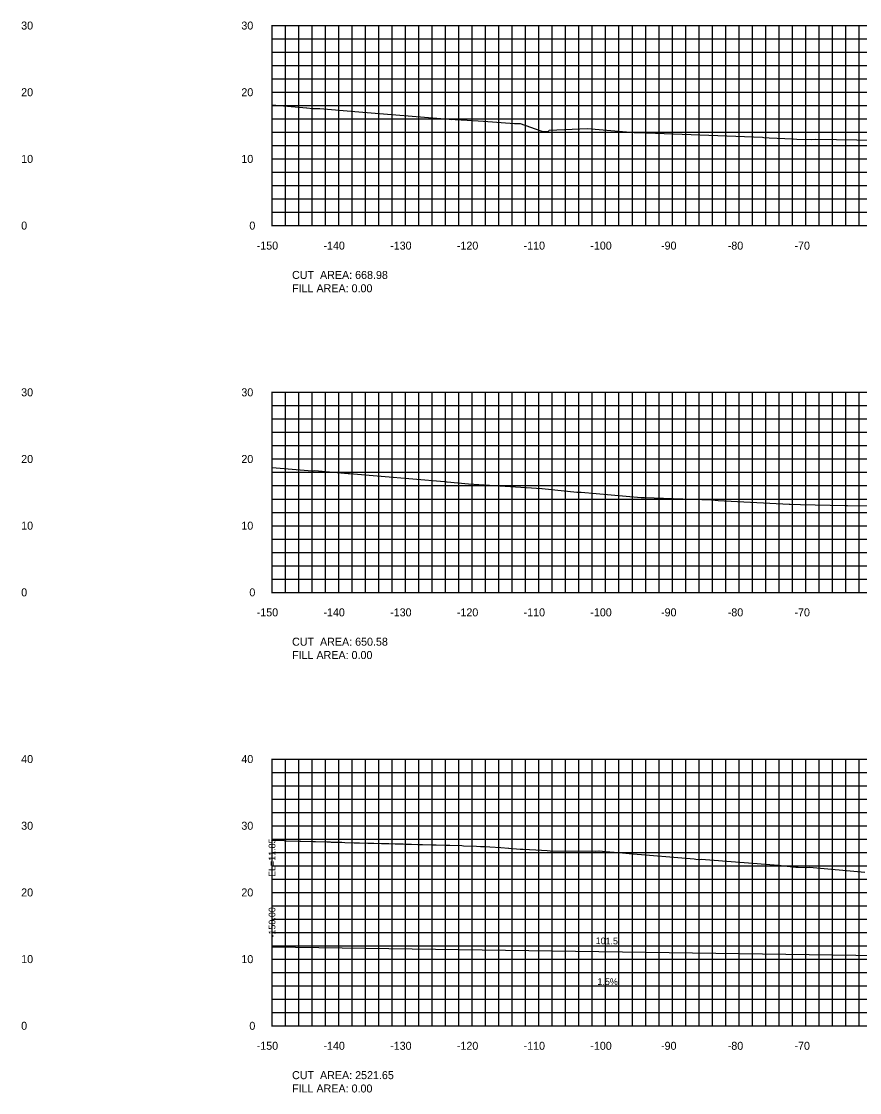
# Model space of a CAD drawing. Extents: x 1797789 to 1803805, y 249066 to 250293.
# Drawn here: x 1803123.4 to 1803249.1, y 250089.4 to 250250 of the extents above; entities that cross this region are included whole.
import ezdxf

# ---------------------------------------------------------------- set-up
doc = ezdxf.new("R2010")
doc.units = 0
for name, color, linetype in [('10', 7, 'Continuous'), ('3', 7, 'Continuous'), ('31', 7, 'Continuous'), ('4', 7, 'Continuous'), ('60', 7, 'Continuous'), ('ANNO-TXT', 7, 'Continuous'), ('CL-CNST', 7, 'Continuous'), ('Level 62', 7, 'Continuous'), ('M-ROADS', 7, 'Continuous')]:
    doc.layers.add(name, color=color, linetype=linetype)

msp = doc.modelspace()

# ---------------------------------------------------------------- linework, layer by layer
msp.add_line((1803161, 250111.29), (1803161, 250113.29))
at = {"layer": '60'}
for p, q in [((1803160.94, 250249.43), (1803161, 250249.43)), ((1803161, 250219.43), (1803161, 250249.43)), ((1803160.94, 250239.43), (1803161, 250239.43)), ((1803160.94, 250229.43), (1803161, 250229.43)), ((1803160.94, 250219.43), (1803161, 250219.43)), ((1803161, 250219.43), (1803461, 250219.43)), ((1803161, 250219.37), (1803161, 250219.43)), ((1803171, 250219.37), (1803171, 250219.43)), ((1803181, 250219.37), (1803181, 250219.43)), ((1803191, 250219.37), (1803191, 250219.43)), ((1803201, 250219.37), (1803201, 250219.43)), ((1803211, 250219.37), (1803211, 250219.43)), ((1803221, 250219.37), (1803221, 250219.43)), ((1803231, 250219.37), (1803231, 250219.43)), ((1803241, 250219.37), (1803241, 250219.43)), ((1803160.94, 250194.43), (1803161, 250194.43)), ((1803161, 250164.43), (1803161, 250194.43)), ((1803160.94, 250184.43), (1803161, 250184.43)), ((1803160.94, 250174.43), (1803161, 250174.43)), ((1803160.94, 250164.43), (1803161, 250164.43)), ((1803161, 250164.43), (1803461, 250164.43)), ((1803161, 250164.37), (1803161, 250164.43)), ((1803171, 250164.37), (1803171, 250164.43)), ((1803181, 250164.37), (1803181, 250164.43)), ((1803191, 250164.37), (1803191, 250164.43)), ((1803201, 250164.37), (1803201, 250164.43)), ((1803211, 250164.37), (1803211, 250164.43)), ((1803221, 250164.37), (1803221, 250164.43)), ((1803231, 250164.37), (1803231, 250164.43)), ((1803241, 250164.37), (1803241, 250164.43)), ((1803160.94, 250139.43), (1803161, 250139.43)), ((1803161, 250099.43), (1803161, 250139.43)), ((1803160.94, 250129.43), (1803161, 250129.43)), ((1803160.94, 250119.43), (1803161, 250119.43)), ((1803160.94, 250109.43), (1803161, 250109.43)), ((1803160.94, 250099.43), (1803161, 250099.43)), ((1803161, 250099.43), (1803461, 250099.43)), ((1803161, 250099.37), (1803161, 250099.43)), ((1803171, 250099.37), (1803171, 250099.43)), ((1803181, 250099.37), (1803181, 250099.43)), ((1803191, 250099.37), (1803191, 250099.43)), ((1803201, 250099.37), (1803201, 250099.43)), ((1803211, 250099.37), (1803211, 250099.43)), ((1803221, 250099.37), (1803221, 250099.43)), ((1803231, 250099.37), (1803231, 250099.43)), ((1803241, 250099.37), (1803241, 250099.43))]:
    msp.add_line(p, q, dxfattribs=at)
at = {"layer": 'CL-CNST'}
msp.add_lwpolyline([(1803161, 250111.29), (1803262.5, 250109.8), (1803263.5, 250109.76), (1803270.5, 250109.65), (1803270.5, 250109.65), (1803270.83, 250109.65), (1803271, 250109.15), (1803273, 250109.31), (1803277, 250109.4), (1803311, 250110.15), (1803345, 250109.4), (1803349, 250109.31), (1803351, 250109.15), (1803351.17, 250109.65), (1803351.5, 250109.65), (1803351.5, 250109.65), (1803358.5, 250109.76), (1803359.5, 250109.8), (1803461, 250109.89)], dxfattribs=at)
at = {"layer": 'Level 62'}
for p, q in [((1803161, 250249.43), (1803461, 250249.43)), ((1803161, 250219.43), (1803161, 250249.43)), ((1803163, 250219.43), (1803163, 250249.43)), ((1803165, 250219.43), (1803165, 250249.43)), ((1803167, 250219.43), (1803167, 250249.43)), ((1803169, 250219.43), (1803169, 250249.43)), ((1803171, 250219.43), (1803171, 250249.43)), ((1803173, 250219.43), (1803173, 250249.43)), ((1803175, 250219.43), (1803175, 250249.43)), ((1803177, 250219.43), (1803177, 250249.43)), ((1803179, 250219.43), (1803179, 250249.43)), ((1803181, 250219.43), (1803181, 250249.43)), ((1803183, 250219.43), (1803183, 250249.43)), ((1803185, 250219.43), (1803185, 250249.43)), ((1803187, 250219.43), (1803187, 250249.43)), ((1803189, 250219.43), (1803189, 250249.43)), ((1803191, 250219.43), (1803191, 250249.43)), ((1803193, 250219.43), (1803193, 250249.43)), ((1803195, 250219.43), (1803195, 250249.43)), ((1803197, 250219.43), (1803197, 250249.43)), ((1803199, 250219.43), (1803199, 250249.43)), ((1803201, 250219.43), (1803201, 250249.43)), ((1803203, 250219.43), (1803203, 250249.43)), ((1803205, 250219.43), (1803205, 250249.43)), ((1803207, 250219.43), (1803207, 250249.43)), ((1803209, 250219.43), (1803209, 250249.43)), ((1803211, 250219.43), (1803211, 250249.43)), ((1803213, 250219.43), (1803213, 250249.43)), ((1803215, 250219.43), (1803215, 250249.43)), ((1803217, 250219.43), (1803217, 250249.43)), ((1803219, 250219.43), (1803219, 250249.43)), ((1803221, 250219.43), (1803221, 250249.43)), ((1803223, 250219.43), (1803223, 250249.43)), ((1803225, 250219.43), (1803225, 250249.43)), ((1803227, 250219.43), (1803227, 250249.43)), ((1803229, 250219.43), (1803229, 250249.43)), ((1803231, 250219.43), (1803231, 250249.43)), ((1803233, 250219.43), (1803233, 250249.43)), ((1803235, 250219.43), (1803235, 250249.43)), ((1803237, 250219.43), (1803237, 250249.43)), ((1803239, 250219.43), (1803239, 250249.43)), ((1803241, 250219.43), (1803241, 250249.43)), ((1803243, 250219.43), (1803243, 250249.43)), ((1803245, 250219.43), (1803245, 250249.43)), ((1803247, 250219.43), (1803247, 250249.43)), ((1803249, 250219.43), (1803249, 250249.43)), ((1803161, 250247.43), (1803461, 250247.43)), ((1803161, 250245.43), (1803461, 250245.43)), ((1803161, 250243.43), (1803461, 250243.43)), ((1803161, 250241.43), (1803461, 250241.43)), ((1803161, 250239.43), (1803461, 250239.43)), ((1803161, 250237.43), (1803461, 250237.43)), ((1803161, 250235.43), (1803461, 250235.43)), ((1803161, 250233.43), (1803461, 250233.43)), ((1803161, 250231.43), (1803461, 250231.43)), ((1803161, 250229.43), (1803461, 250229.43)), ((1803161, 250227.43), (1803461, 250227.43)), ((1803161, 250225.43), (1803461, 250225.43)), ((1803161, 250223.43), (1803461, 250223.43)), ((1803161, 250221.43), (1803461, 250221.43)), ((1803161, 250219.43), (1803461, 250219.43)), ((1803161, 250194.43), (1803461, 250194.43)), ((1803161, 250164.43), (1803161, 250194.43)), ((1803163, 250164.43), (1803163, 250194.43)), ((1803165, 250164.43), (1803165, 250194.43)), ((1803167, 250164.43), (1803167, 250194.43)), ((1803169, 250164.43), (1803169, 250194.43)), ((1803171, 250164.43), (1803171, 250194.43)), ((1803173, 250164.43), (1803173, 250194.43)), ((1803175, 250164.43), (1803175, 250194.43)), ((1803177, 250164.43), (1803177, 250194.43)), ((1803179, 250164.43), (1803179, 250194.43)), ((1803181, 250164.43), (1803181, 250194.43)), ((1803183, 250164.43), (1803183, 250194.43)), ((1803185, 250164.43), (1803185, 250194.43)), ((1803187, 250164.43), (1803187, 250194.43)), ((1803189, 250164.43), (1803189, 250194.43)), ((1803191, 250164.43), (1803191, 250194.43)), ((1803193, 250164.43), (1803193, 250194.43)), ((1803195, 250164.43), (1803195, 250194.43)), ((1803197, 250164.43), (1803197, 250194.43)), ((1803199, 250164.43), (1803199, 250194.43)), ((1803201, 250164.43), (1803201, 250194.43)), ((1803203, 250164.43), (1803203, 250194.43)), ((1803205, 250164.43), (1803205, 250194.43)), ((1803207, 250164.43), (1803207, 250194.43)), ((1803209, 250164.43), (1803209, 250194.43)), ((1803211, 250164.43), (1803211, 250194.43)), ((1803213, 250164.43), (1803213, 250194.43)), ((1803215, 250164.43), (1803215, 250194.43)), ((1803217, 250164.43), (1803217, 250194.43)), ((1803219, 250164.43), (1803219, 250194.43)), ((1803221, 250164.43), (1803221, 250194.43)), ((1803223, 250164.43), (1803223, 250194.43)), ((1803225, 250164.43), (1803225, 250194.43)), ((1803227, 250164.43), (1803227, 250194.43)), ((1803229, 250164.43), (1803229, 250194.43)), ((1803231, 250164.43), (1803231, 250194.43)), ((1803233, 250164.43), (1803233, 250194.43)), ((1803235, 250164.43), (1803235, 250194.43)), ((1803237, 250164.43), (1803237, 250194.43)), ((1803239, 250164.43), (1803239, 250194.43)), ((1803241, 250164.43), (1803241, 250194.43)), ((1803243, 250164.43), (1803243, 250194.43)), ((1803245, 250164.43), (1803245, 250194.43)), ((1803247, 250164.43), (1803247, 250194.43)), ((1803249, 250164.43), (1803249, 250194.43)), ((1803161, 250192.43), (1803461, 250192.43)), ((1803161, 250190.43), (1803461, 250190.43)), ((1803161, 250188.43), (1803461, 250188.43)), ((1803161, 250186.43), (1803461, 250186.43)), ((1803161, 250184.43), (1803461, 250184.43)), ((1803161, 250182.43), (1803461, 250182.43)), ((1803161, 250180.43), (1803461, 250180.43)), ((1803161, 250178.43), (1803461, 250178.43)), ((1803161, 250176.43), (1803461, 250176.43)), ((1803161, 250174.43), (1803461, 250174.43)), ((1803161, 250172.43), (1803461, 250172.43)), ((1803161, 250170.43), (1803461, 250170.43)), ((1803161, 250168.43), (1803461, 250168.43)), ((1803161, 250166.43), (1803461, 250166.43)), ((1803161, 250164.43), (1803461, 250164.43)), ((1803161, 250139.43), (1803461, 250139.43)), ((1803161, 250099.43), (1803161, 250139.43)), ((1803163, 250099.43), (1803163, 250139.43)), ((1803165, 250099.43), (1803165, 250139.43)), ((1803167, 250099.43), (1803167, 250139.43)), ((1803169, 250099.43), (1803169, 250139.43)), ((1803171, 250099.43), (1803171, 250139.43)), ((1803173, 250099.43), (1803173, 250139.43)), ((1803175, 250099.43), (1803175, 250139.43)), ((1803177, 250099.43), (1803177, 250139.43)), ((1803179, 250099.43), (1803179, 250139.43)), ((1803181, 250099.43), (1803181, 250139.43)), ((1803183, 250099.43), (1803183, 250139.43)), ((1803185, 250099.43), (1803185, 250139.43)), ((1803187, 250099.43), (1803187, 250139.43)), ((1803189, 250099.43), (1803189, 250139.43)), ((1803191, 250099.43), (1803191, 250139.43)), ((1803193, 250099.43), (1803193, 250139.43)), ((1803195, 250099.43), (1803195, 250139.43)), ((1803197, 250099.43), (1803197, 250139.43)), ((1803199, 250099.43), (1803199, 250139.43)), ((1803201, 250099.43), (1803201, 250139.43)), ((1803203, 250099.43), (1803203, 250139.43)), ((1803205, 250099.43), (1803205, 250139.43)), ((1803207, 250099.43), (1803207, 250139.43)), ((1803209, 250099.43), (1803209, 250139.43)), ((1803211, 250099.43), (1803211, 250139.43)), ((1803213, 250099.43), (1803213, 250139.43)), ((1803215, 250099.43), (1803215, 250139.43)), ((1803217, 250099.43), (1803217, 250139.43)), ((1803219, 250099.43), (1803219, 250139.43)), ((1803221, 250099.43), (1803221, 250139.43)), ((1803223, 250099.43), (1803223, 250139.43)), ((1803225, 250099.43), (1803225, 250139.43)), ((1803227, 250099.43), (1803227, 250139.43)), ((1803229, 250099.43), (1803229, 250139.43)), ((1803231, 250099.43), (1803231, 250139.43)), ((1803233, 250099.43), (1803233, 250139.43)), ((1803235, 250099.43), (1803235, 250139.43)), ((1803237, 250099.43), (1803237, 250139.43)), ((1803239, 250099.43), (1803239, 250139.43)), ((1803241, 250099.43), (1803241, 250139.43)), ((1803243, 250099.43), (1803243, 250139.43)), ((1803245, 250099.43), (1803245, 250139.43)), ((1803247, 250099.43), (1803247, 250139.43)), ((1803249, 250099.43), (1803249, 250139.43)), ((1803161, 250137.43), (1803461, 250137.43)), ((1803161, 250135.43), (1803461, 250135.43)), ((1803161, 250133.43), (1803461, 250133.43)), ((1803161, 250131.43), (1803461, 250131.43)), ((1803161, 250129.43), (1803461, 250129.43)), ((1803161, 250127.43), (1803461, 250127.43)), ((1803161, 250125.43), (1803461, 250125.43)), ((1803161, 250123.43), (1803461, 250123.43)), ((1803161, 250121.43), (1803461, 250121.43)), ((1803161, 250119.43), (1803461, 250119.43)), ((1803161, 250117.43), (1803461, 250117.43)), ((1803161, 250115.43), (1803461, 250115.43)), ((1803161, 250113.43), (1803461, 250113.43)), ((1803161, 250111.43), (1803461, 250111.43)), ((1803161, 250109.43), (1803461, 250109.43)), ((1803161, 250107.43), (1803461, 250107.43)), ((1803161, 250105.43), (1803461, 250105.43)), ((1803161, 250103.43), (1803461, 250103.43)), ((1803161, 250101.43), (1803461, 250101.43)), ((1803161, 250099.43), (1803461, 250099.43))]:
    msp.add_line(p, q, dxfattribs=at)
at = {"layer": 'M-ROADS'}
for points in [[(1803161, 250237.55), (1803166.15, 250237.11), (1803166.19, 250237.1), (1803167.08, 250236.99), (1803167.31, 250236.97), (1803167.32, 250236.97), (1803167.71, 250237.01), (1803168.12, 250236.98), (1803168.14, 250236.98), (1803173.99, 250236.49), (1803187.56, 250235.38), (1803187.92, 250235.34), (1803188.29, 250235.37), (1803188.45, 250235.36), (1803189.36, 250235.31), (1803189.59, 250235.28), (1803190.26, 250235.22), (1803192.7, 250235.07), (1803197.36, 250234.76), (1803197.54, 250234.75), (1803198.17, 250234.74), (1803201.27, 250233.62), (1803201.68, 250233.54), (1803201.75, 250233.54), (1803202.01, 250233.54), (1803202.13, 250233.53), (1803202.28, 250233.52), (1803202.45, 250233.53), (1803202.53, 250233.72), (1803208.29, 250233.97), (1803215.29, 250233.37), (1803215.37, 250233.37), (1803215.77, 250233.39), (1803234.52, 250232.67), (1803234.72, 250232.66), (1803235.49, 250232.61), (1803239.06, 250232.42), (1803239.11, 250232.42), (1803239.64, 250232.4), (1803241.88, 250232.36), (1803242.49, 250232.37), (1803257.91, 250232.13)], [(1803161, 250183.17), (1803167.02, 250182.64), (1803167.16, 250182.66), (1803167.42, 250182.68), (1803172.41, 250182.23), (1803172.62, 250182.24), (1803186.85, 250181.04), (1803187.16, 250180.99), (1803187.25, 250180.98), (1803190.46, 250180.72), (1803201.41, 250179.99), (1803201.47, 250180), (1803206.69, 250179.45), (1803207.32, 250179.44), (1803216.34, 250178.66), (1803216.6, 250178.67), (1803216.82, 250178.67), (1803226.86, 250178.29), (1803227.41, 250178.26), (1803227.84, 250178.23), (1803238.51, 250177.65), (1803238.64, 250177.66), (1803240.21, 250177.59), (1803246.84, 250177.48), (1803247.25, 250177.48), (1803257.62, 250177.32)], [(1803161, 250127.26), (1803162.8, 250127.2), (1803163.09, 250127.19), (1803163.11, 250127.19), (1803165.14, 250127.13), (1803165.27, 250127.13), (1803165.3, 250127.13), (1803167.18, 250127.07), (1803167.5, 250127.06), (1803169.23, 250127.01), (1803169.69, 250127), (1803169.84, 250126.99), (1803171.44, 250126.95), (1803171.89, 250126.93), (1803173.33, 250126.89), (1803174.09, 250126.87), (1803175.37, 250126.83), (1803176.07, 250126.81), (1803176.28, 250126.8), (1803177.42, 250126.77), (1803178.48, 250126.75), (1803179.47, 250126.72), (1803180.67, 250126.7), (1803181.05, 250126.69), (1803181.88, 250126.67), (1803182.87, 250126.64), (1803183.56, 250126.63), (1803185.07, 250126.59), (1803185.6, 250126.57), (1803186.88, 250126.54), (1803187.26, 250126.52), (1803187.65, 250126.51), (1803189.46, 250126.45), (1803189.69, 250126.44), (1803191.65, 250126.37), (1803192.26, 250126.34), (1803192.3, 250126.34), (1803192.86, 250126.32), (1803193.65, 250126.27), (1803193.66, 250126.27), (1803195.31, 250126.16), (1803196.44, 250126.07), (1803196.5, 250126.06), (1803198.19, 250125.94), (1803198.63, 250125.92), (1803200.53, 250125.81), (1803202.22, 250125.71), (1803202.66, 250125.69), (1803209.54, 250125.63), (1803210, 250125.65), (1803210.05, 250125.66), (1803211.04, 250125.59), (1803213.5, 250125.38), (1803214.52, 250125.28), (1803224.29, 250124.47), (1803224.53, 250124.44), (1803224.98, 250124.39), (1803225.11, 250124.38), (1803225.34, 250124.4), (1803236.91, 250123.5), (1803237.75, 250123.42), (1803239.51, 250123.23), (1803239.66, 250123.22), (1803239.85, 250123.2), (1803241.03, 250123.17), (1803241.09, 250123.18), (1803241.54, 250123.2), (1803249.84, 250122.48)]]:
    msp.add_lwpolyline(points, dxfattribs=at)

# ---------------------------------------------------------------- texts
at = {"layer": '10'}
for s, p in [('-150', (1803158.7, 250215.83)), ('-140', (1803168.7, 250215.83)), ('-130', (1803178.7, 250215.83)), ('-120', (1803188.7, 250215.83)), ('-110', (1803198.7, 250215.83)), ('-100', (1803208.7, 250215.83)), ('-90', (1803219.3, 250215.83)), ('-80', (1803229.3, 250215.83)), ('-70', (1803239.3, 250215.83)), ('-150', (1803158.7, 250160.83)), ('-140', (1803168.7, 250160.83)), ('-130', (1803178.7, 250160.83)), ('-120', (1803188.7, 250160.83)), ('-110', (1803198.7, 250160.83)), ('-100', (1803208.7, 250160.83)), ('-90', (1803219.3, 250160.83)), ('-80', (1803229.3, 250160.83)), ('-70', (1803239.3, 250160.83)), ('-150', (1803158.7, 250095.83)), ('-140', (1803168.7, 250095.83)), ('-130', (1803178.7, 250095.83)), ('-120', (1803188.7, 250095.83)), ('-110', (1803198.7, 250095.83)), ('-100', (1803208.7, 250095.83)), ('-90', (1803219.3, 250095.83)), ('-80', (1803229.3, 250095.83)), ('-70', (1803239.3, 250095.83))]:
    msp.add_text(s, height=1.2, dxfattribs=at).set_placement(p)
at = {"layer": '3'}
for s, p in [('EL=11.85', (1803161.5, 250121.76)), ('-150.00', (1803161.5, 250112.67))]:
    msp.add_text(s, height=1, rotation=90, dxfattribs=at).set_placement(p)
at = {"layer": '31'}
for s, p in [('30', (1803123.4, 250248.83)), ('30', (1803156.4, 250248.83)), ('20', (1803123.4, 250238.83)), ('20', (1803156.4, 250238.83)), ('10', (1803123.4, 250228.83)), ('10', (1803156.4, 250228.83)), ('0', (1803123.4, 250218.83)), ('0', (1803157.6, 250218.83)), ('30', (1803123.4, 250193.83)), ('30', (1803156.4, 250193.83)), ('20', (1803123.4, 250183.83)), ('20', (1803156.4, 250183.83)), ('10', (1803123.4, 250173.83)), ('10', (1803156.4, 250173.83)), ('0', (1803123.4, 250163.83)), ('0', (1803157.6, 250163.83)), ('40', (1803123.4, 250138.83)), ('40', (1803156.4, 250138.83)), ('30', (1803123.4, 250128.83)), ('30', (1803156.4, 250128.83)), ('20', (1803123.4, 250118.83)), ('20', (1803156.4, 250118.83)), ('10', (1803123.4, 250108.83)), ('10', (1803156.4, 250108.83)), ('0', (1803123.4, 250098.83)), ('0', (1803157.6, 250098.83))]:
    msp.add_text(s, height=1.2, dxfattribs=at).set_placement(p)
at = {"layer": '4'}
for s, p in [('101.5', (1803209.49, 250111.68)), ('1.5%', (1803209.77, 250105.57))]:
    msp.add_text(s, height=1, rotation=359.1608, dxfattribs=at).set_placement(p)
at = {"layer": '60'}
for p in [(1803161, 250219.43), (1803161, 250164.43), (1803161, 250099.43)]:
    msp.add_text('-', height=0.0001, dxfattribs=at).set_placement(p)
at = {"layer": 'ANNO-TXT'}
for s, p in [('CUT  AREA: 668.98', (1803164, 250211.43)), ('FILL AREA: 0.00', (1803164, 250209.43)), ('CUT  AREA: 650.58', (1803164, 250156.43)), ('FILL AREA: 0.00', (1803164, 250154.43)), ('CUT  AREA: 2521.65', (1803164, 250091.43)), ('FILL AREA: 0.00', (1803164, 250089.43))]:
    msp.add_text(s, height=1.2, dxfattribs=at).set_placement(p)

doc.saveas('drawing.dxf')
